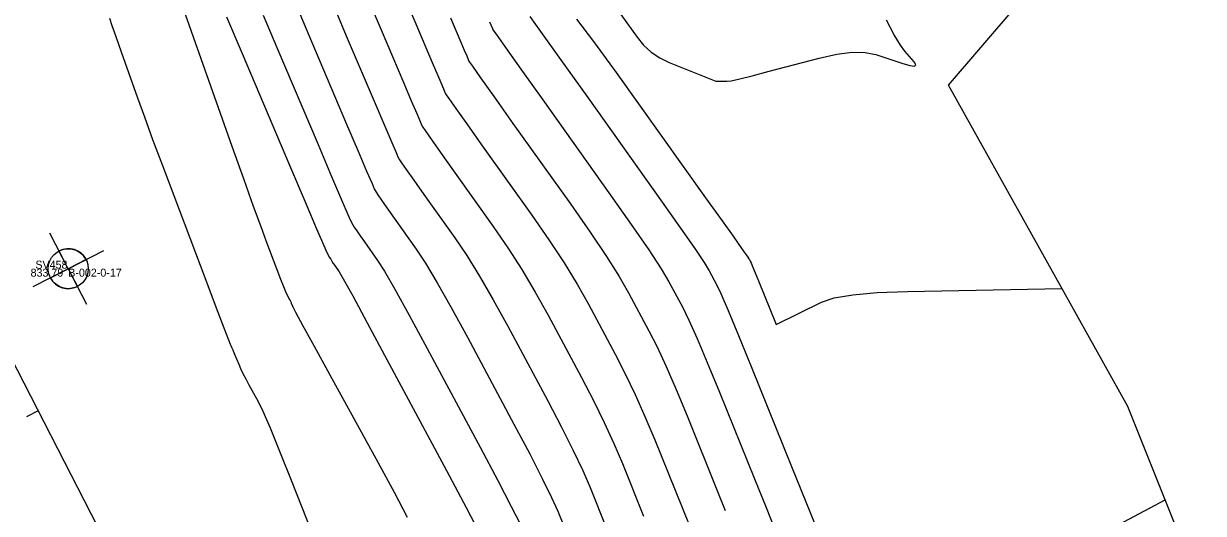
# Model space of a CAD drawing. Extents: x 1715724 to 1716561, y 394063 to 395906.
# Drawn here: x 1716070.7 to 1716159.2, y 395022.9 to 395059.6 of the extents above; entities that cross this region are included whole.
import ezdxf

# ---------------------------------------------------------------- set-up
doc = ezdxf.new("R2010")
doc.units = 0
for name, color, linetype in [('DT_X_Contour_Major', 7, 'Continuous'), ('DT_X_Contour_Minor', 7, 'Continuous'), ('DT_X_TIN_Hull', 7, 'Continuous'), ('GE_P_CL_10', 7, 'Continuous'), ('GT_Project_Soil_Boring', 7, 'Continuous'), ('SV_X_Text_Comment', 7, 'Continuous'), ('SV_X_Text_Elevation', 7, 'Continuous'), ('SV_X_Text_Name', 7, 'Continuous')]:
    doc.layers.add(name, color=color, linetype=linetype)

msp = doc.modelspace()

# ---------------------------------------------------------------- linework, layer by layer
at = {"layer": 'DT_X_Contour_Major'}
for points in [[(1716088.665, 395060.216), (1716089.693, 395057.798), (1716092.783, 395050.525), (1716093.805, 395048.124), (1716094.554, 395046.374), (1716095.028, 395045.275), (1716095.23, 395044.828), (1716095.402, 395044.505), (1716095.505, 395044.335), (1716095.684, 395044.064), (1716095.939, 395043.694), (1716096.271, 395043.225), (1716097.256, 395041.84), (1716097.766, 395041.039), (1716098.555, 395039.671), (1716099.624, 395037.739), (1716100.973, 395035.241), (1716104.942, 395027.825), (1716106.27, 395025.328), (1716107.278, 395023.398), (1716107.966, 395022.035)], [(1716102.723, 395060.019), (1716103.495, 395058.204), (1716103.75, 395057.605), (1716103.937, 395057.168), (1716104.055, 395056.894), (1716104.105, 395056.782), (1716104.148, 395056.701), (1716104.364, 395056.392), (1716104.979, 395055.524), (1716105.993, 395054.097), (1716107.406, 395052.111), (1716111.707, 395046.072), (1716113.19, 395043.956), (1716114.413, 395042.14), (1716115.375, 395040.622), (1716116.078, 395039.403), (1716117.604, 395036.552), (1716118.212, 395035.352), (1716118.891, 395033.888), (1716119.641, 395032.163), (1716120.462, 395030.175), (1716122.746, 395024.523), (1716123.33, 395023.079)]]:
    msp.add_lwpolyline(points, dxfattribs=at)
at = {"layer": 'DT_X_Contour_Minor'}
for points in [[(1716081.823, 395063.163), (1716086.328, 395050.409), (1716087.211, 395047.917), (1716087.93, 395045.904), (1716088.484, 395044.373), (1716088.874, 395043.321), (1716089.694, 395041.158), (1716089.97, 395040.435), (1716090.184, 395039.889), (1716090.335, 395039.519), (1716090.424, 395039.326), (1716090.577, 395039.048), (1716090.632, 395038.943), (1716090.684, 395038.839), (1716090.733, 395038.736), (1716090.777, 395038.633), (1716090.892, 395038.36), (1716091.098, 395037.964), (1716091.631, 395036.98), (1716092.489, 395035.41), (1716093.674, 395033.252), (1716097.269, 395026.715), (1716098.493, 395024.459), (1716099.468, 395022.592)], [(1716096.918, 395060.521), (1716097.511, 395059.131), (1716099.21, 395055.133), (1716099.772, 395053.812), (1716100.183, 395052.85), (1716100.444, 395052.246), (1716100.555, 395052.001), (1716100.65, 395051.823), (1716100.82, 395051.569), (1716101.261, 395050.94), (1716101.971, 395049.936), (1716102.952, 395048.557), (1716105.927, 395044.379), (1716107.02, 395042.789), (1716108.07, 395041.152), (1716109.075, 395039.469), (1716110.036, 395037.738), (1716112.539, 395033.061), (1716113.435, 395031.342), (1716114.246, 395029.692), (1716114.971, 395028.112), (1716115.61, 395026.6), (1716117.202, 395022.662)], [(1716099.67, 395060.623), (1716100.117, 395059.575), (1716101.352, 395056.668), (1716101.761, 395055.708), (1716102.06, 395055.009), (1716102.25, 395054.57), (1716102.33, 395054.391), (1716102.399, 395054.262), (1716102.592, 395053.98), (1716103.12, 395053.232), (1716103.982, 395052.016), (1716105.179, 395050.334), (1716108.817, 395045.225), (1716110.105, 395043.373), (1716111.241, 395041.646), (1716112.225, 395040.046), (1716113.057, 395038.571), (1716115.071, 395034.807), (1716115.823, 395033.347), (1716116.568, 395031.79), (1716117.306, 395030.137), (1716118.036, 395028.387), (1716120.61, 395022.017)], [(1716095.52, 395013.365), (1716090.841, 395025.218), (1716089.932, 395027.499), (1716089.208, 395029.262), (1716088.671, 395030.508), (1716088.32, 395031.236), (1716087.632, 395032.486), (1716087.391, 395032.934), (1716087.182, 395033.34), (1716087.006, 395033.705), (1716086.863, 395034.028), (1716086.525, 395034.835), (1716086.413, 395035.102), (1716086.329, 395035.299), (1716086.274, 395035.427), (1716086.248, 395035.484), (1716086.216, 395035.542), (1716086.093, 395035.858), (1716085.747, 395036.763), (1716085.18, 395038.257), (1716084.39, 395040.34), (1716081.987, 395046.68), (1716081.141, 395048.921), (1716080.407, 395050.891), (1716079.784, 395052.589), (1716079.273, 395054.015), (1716078.057, 395057.456), (1716077.654, 395058.596), (1716077.357, 395059.436), (1716077.166, 395059.975)], [(1716085.913, 395060.114), (1716087.087, 395057.353), (1716090.641, 395048.989), (1716091.816, 395046.227), (1716092.677, 395044.215), (1716093.223, 395042.952), (1716093.455, 395042.438), (1716093.653, 395042.066), (1716093.733, 395041.923), (1716093.825, 395041.772), (1716093.928, 395041.614), (1716094.043, 395041.448), (1716094.366, 395040.994), (1716094.681, 395040.455), (1716095.384, 395039.178), (1716096.474, 395037.162), (1716097.952, 395034.408), (1716102.409, 395026.08), (1716103.882, 395023.324), (1716104.955, 395021.3)], [(1716091.416, 395060.317), (1716092.299, 395058.242), (1716094.925, 395052.061), (1716095.794, 395050.02), (1716096.43, 395048.533), (1716096.834, 395047.599), (1716097.005, 395047.219), (1716097.151, 395046.945), (1716097.277, 395046.746), (1716097.543, 395046.356), (1716097.95, 395045.775), (1716098.498, 395045.002), (1716100.147, 395042.687), (1716100.851, 395041.622), (1716101.727, 395040.165), (1716102.774, 395038.315), (1716103.994, 395036.073), (1716107.474, 395029.571), (1716108.658, 395027.333), (1716109.6, 395025.496), (1716110.301, 395024.06), (1716110.759, 395023.026), (1716111.658, 395020.801)], [(1716094.167, 395060.419), (1716094.905, 395058.686), (1716097.068, 395053.597), (1716097.783, 395051.916), (1716098.307, 395050.691), (1716098.639, 395049.923), (1716098.78, 395049.61), (1716098.901, 395049.384), (1716099.049, 395049.157), (1716099.402, 395048.648), (1716099.961, 395047.855), (1716100.725, 395046.779), (1716103.037, 395043.533), (1716103.936, 395042.206), (1716104.898, 395040.659), (1716105.925, 395038.892), (1716107.015, 395036.906), (1716110.007, 395031.316), (1716111.047, 395029.338), (1716111.923, 395027.594), (1716112.636, 395026.086), (1716113.184, 395024.813), (1716114.43, 395021.731)], [(1716105.637, 395059.74), (1716105.739, 395059.501), (1716105.86, 395059.217), (1716105.881, 395059.173), (1716105.898, 395059.141), (1716106.136, 395058.803), (1716106.838, 395057.816), (1716108.004, 395056.177), (1716109.633, 395053.889), (1716114.597, 395046.918), (1716116.275, 395044.54), (1716117.584, 395042.634), (1716118.525, 395041.199), (1716119.099, 395040.236), (1716120.136, 395038.297), (1716120.6, 395037.356), (1716121.213, 395035.987), (1716121.976, 395034.188), (1716122.887, 395031.962), (1716125.518, 395025.453), (1716126.381, 395023.317), (1716126.999, 395021.789)], [(1716108.669, 395060.126), (1716109.093, 395059.54), (1716110.973, 395056.909), (1716113.008, 395054.054), (1716118.589, 395046.217), (1716119.979, 395044.253), (1716121.031, 395042.74), (1716121.744, 395041.679), (1716122.12, 395041.069), (1716122.669, 395040.043), (1716122.988, 395039.361), (1716123.536, 395038.085), (1716124.311, 395036.214), (1716125.313, 395033.749), (1716128.29, 395026.383), (1716130.384, 395021.202)], [(1716112.168, 395059.93), (1716113.451, 395058.246), (1716115.137, 395055.924), (1716120.173, 395048.879), (1716121.846, 395046.537), (1716123.091, 395044.795), (1716123.907, 395043.654), (1716124.293, 395043.112), (1716124.751, 395042.469), (1716124.905, 395042.252), (1716125.021, 395042.085), (1716125.099, 395041.968), (1716125.141, 395041.901), (1716125.201, 395041.788), (1716125.256, 395041.663), (1716125.377, 395041.374), (1716125.563, 395040.919), (1716125.814, 395040.3), (1716127.137, 395037.026), (1716130.554, 395038.704), (1716131.505, 395039.025), (1716132.894, 395039.268), (1716134.721, 395039.432), (1716136.985, 395039.518), (1716148.573, 395039.739)], [(1716115.491, 395060.268), (1716116.707, 395058.568), (1716117.199, 395057.972), (1716117.766, 395057.46), (1716118.406, 395057.031), (1716119.12, 395056.686), (1716122.624, 395055.271), (1716123.443, 395055.27), (1716123.772, 395055.317), (1716124.41, 395055.457), (1716125.355, 395055.69), (1716126.608, 395056.017), (1716130.36, 395057.013), (1716131.682, 395057.309), (1716132.833, 395057.452), (1716133.815, 395057.44), (1716134.626, 395057.273), (1716136.563, 395056.624), (1716137.165, 395056.448), (1716137.52, 395056.408), (1716137.628, 395056.504), (1716137.488, 395056.735), (1716136.785, 395057.532), (1716136.457, 395057.989), (1716135.998, 395058.761), (1716135.408, 395059.848)], [(1716147.805, 395019.354), (1716156.306, 395023.891)]]:
    msp.add_lwpolyline(points, dxfattribs=at)
at = {"layer": 'DT_X_TIN_Hull'}
msp.add_lwpolyline([(1716173.813, 394948.174), (1716164.239, 394964.103), (1716158.601, 394970.074), (1716161.282, 395011.431), (1716153.509, 395030.897), (1716140.066, 395054.98), (1716157.64, 395075.485), (1716176.813, 395091.39), (1716197.289, 395109.746), (1716218.016, 395125.434), (1716237.91, 395140.502), (1716261.28, 395153.338), (1716300.311, 395170.239), (1716324.758, 395179.267), (1716349.419, 395190.186), (1716344.962, 395206.213), (1716337.659, 395219.828)], dxfattribs=at)
at = {"layer": 'GE_P_CL_10'}
for p, q in [((1716249.46, 394685.42), (1715852.538, 395456.564)), ((1716071.804, 395030.572), (1716070.915, 395030.115))]:
    msp.add_line(p, q, dxfattribs=at)
at = {"layer": 'GT_Project_Soil_Boring'}
for p, q in [((1716074.051, 395041.22), (1716072.678, 395043.887)), ((1716074.051, 395041.22), (1716073.365, 395042.553)), ((1716074.051, 395041.22), (1716076.719, 395042.593)), ((1716075.385, 395041.906), (1716074.051, 395041.22)), ((1716074.051, 395041.22), (1716071.384, 395039.847)), ((1716072.718, 395040.533), (1716074.051, 395041.22)), ((1716074.051, 395041.22), (1716075.424, 395038.552)), ((1716074.051, 395041.22), (1716074.738, 395039.886))]:
    msp.add_line(p, q, dxfattribs=at)
msp.add_circle((1716074.051, 395041.22), 1.5, dxfattribs=at)
for start, end in [(27.23573, 117.23573), (207.23573, 297.23573)]:
    msp.add_arc((1716074.051, 395041.22), 1.5, start, end, dxfattribs=at)

# ---------------------------------------------------------------- texts
at = {"layer": 'SV_X_Text_Comment'}
msp.add_text('B-002-0-17', height=0.6, dxfattribs=at).set_placement((1716074.051, 395040.62))
at = {"layer": 'SV_X_Text_Elevation'}
msp.add_text('833.79', height=0.6, dxfattribs=at).set_placement((1716071.226, 395040.62))
at = {"layer": 'SV_X_Text_Name'}
msp.add_text('SV458', height=0.6, dxfattribs=at).set_placement((1716071.585, 395041.22))

doc.saveas('drawing.dxf')
